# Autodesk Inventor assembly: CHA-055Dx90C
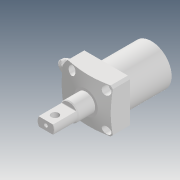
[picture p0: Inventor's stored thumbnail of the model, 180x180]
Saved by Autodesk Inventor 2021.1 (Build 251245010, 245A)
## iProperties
Created: 2019-12
Part Number: CHA-055Dx90C
Description: STEP AP203
Document SubType Name: Assembly
Designer: user
Title: CHA-055Dx90C.STEP
Revision Number: ÈÎºÎ
Sending System: SolidWorks 2017
Preprocessor: SwSTEP 2.0
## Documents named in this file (5)
- D:\Vault_2016\Projekty\Clamptek\Hydraulic\CHA\CHA\CHA-055\Inventor\CHA-055Dx90C\CHA-055Dx90C.iam
- D:\Vault_2016\Projekty\Clamptek\Hydraulic\CHA\CHA\CHA-055\Inventor\CHA-055Dx90C\CHA-055±¾Ìå.ipt
- D:\Vault_2016\Projekty\Clamptek\Hydraulic\CHA\CHA\CHA-055\Inventor\CHA-055Dx90C\CHA-055D»îÈû¸Ë.ipt
- D:\Vault_2016\Projekty\Clamptek\Hydraulic\CHA\CHA\CHA-055\Inventor\CHA-055Dx90C\G1-8¶ÂÍ·.ipt
- D:\Vault_2016\Projekty\Clamptek\Hydraulic\CHA\CHA\CHA-055\Inventor\CHA-055Dx90C\CZL10µ÷ËÙ·§.ipt
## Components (4 placed, 4 different names)
1. CHA-055±¾Ìå_1
2. CHA-055D»îÈû¸Ë_2
3. G1-8¶ÂÍ·_3
4. CZL10µ÷ËÙ·§_4
